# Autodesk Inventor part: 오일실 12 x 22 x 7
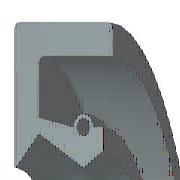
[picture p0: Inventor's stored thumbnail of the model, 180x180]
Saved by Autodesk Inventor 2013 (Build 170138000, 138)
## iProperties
Created: 2012-02
Part Number: 오일실 12 x 22 x 7
Material: 고무
Description: 오일-실
Document SubType Name: Modeling
Standard: KS B 2804
Designer: mduedu
Standards Organization: KS
Language: ko-KR
Size Designation: D - 12 22 7
Categories: <MemberInstance><Categories><Category DisplayName="샤프트 부품" InternalName="7f7aeb1f-a693-4053-b835-cee3144e0d98" Mnemonic="SHFT"><Category DisplayName="실링" Intern
Density: 0.93 g/cm^3
Mass: 1.25383 g
Surface Area: 18.4996 cm^2
Volume: 1.3482 cm^3
IsCustomPart: 1
Author: mduedu
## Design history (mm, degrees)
revolve "본체" stored, may be unused: angle "d17" = 90 deg
revolve "스프링1" stored, may be unused: angle "d18" = 90 deg
body "Solid1"
sketch "스케치1"
  geometry: L1 (0, 11)-(7, 11); L2 (7, 9.25)-(1.75, 9.25); L3 (1.75, 7.75)-(4.9, 6); L4 (4.9, 6)-(0, 6); L5 (0, 0)-(9.586, 0) reference; L6 (4.9, 6)-(6.3, 6.875); L7 (0, 18)-(0, -3) reference; L8 (-1.941, 0)-(11.507, 0) reference; L9 (4.2, 8.1)-(1.75, 8.59); L10 (1.75, 8.59)-(1.75, 9.25); L11 (0, 11)-(0, 6.088); L12 (4.9, 6)-(0, 6); L13 (1.75, 7.75)-(0.152, 6.028); L14 (7, 11)-(7, 9.25); L15 (5.6, 8.1)-(6.3, 8.1); L16 (6.3, 8.1)-(6.3, 6.875); C1 r 0.455 at (4.9, 8.1); A1 r 0.7 centre (4.9, 8.1) between (5.6, 8.1) and (4.2, 8.1); A2 r 0.088 centre (0.088, 6.088) between (0, 6.088) and (0.152, 6.028); 1 further point
  constraints: 28 end point, 5 horizontal alignment, 5 point on line, 4 point on circle, 4 vertical alignment, 3 centre point, 3 tangent, 2 collinear, 2 horizontal, 2 perpendicular, 1 coincident, 1 parallel
  dimensions: "d0" = 22 diameter of L1 L5 (= SD2); "d1" = 1.75 distance of L1.end L2.start (= SD); "d2" = 0.91 diameter of C1 (= SPDI); "d3" = 1.4 diameter of A1 (= SPDA); "d4" = 12 diameter of L3.end L5 (= NND); "d5" = 15.5 diameter of L3.start L5 (= TKDM); "d7" = 17.18 diameter of L9.end L5 (= TKDM + 0.24 x SWDT); "d8" = 1.75 distance between parallel lines of L11 L10 (= SD); "d9" = 4.9 distance from line of L11 C1.centre (= SPDST); "d10" = 16.2 diameter of C1.centre L5 (= HLDM); "d11" = 0.0875 radius of A2 (= 0.25 x LAB); "d12" = 6.3 distance between parallel lines of L11 L16 (= SDI); "d13" = 13.75 diameter of L6.end L5 (= ABDM); "d14" = 7 distance from line of L11 L1.end (= SWDT)
fillet "모깎기1" dims "d6" = 0.3 (= RR)
other parameters: "SD2" = 22 [user parameter; used in 1 equation term], "SWDT" = 7 [user parameter; used in 2 equation terms], "RR" = 0.3 [user parameter; used in 1 equation term], "SD" = 1.75 [user parameter; used in 2 equation terms], "NND" = 12 [user parameter; used in 1 equation term], "SPDA" = 1.4 [user parameter; used in 1 equation term], "SPDI" = 0.91 [user parameter; used in 1 equation term], "TKDM" = 15.5 [user parameter; used in 2 equation terms], "HLDM" = 16.2 [user parameter; used in 1 equation term], "ABDM" = 13.75 [user parameter; used in 1 equation term], "SDI" = 6.3 [user parameter; used in 1 equation term], "SPDST" = 4.9 [user parameter; used in 1 equation term], "LAB" = 0.35 [user parameter; used in 1 equation term], "d15" = 0, "d16" = 0, "d19" = 0
